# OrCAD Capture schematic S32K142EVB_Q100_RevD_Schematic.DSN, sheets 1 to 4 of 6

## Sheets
1 4. OpenSDA interface: size D; title: S32K142EVB-Q100; rev: D; company: Freescale Semiconductor; note: SCH-29701 PDF: SPF-29701; note: 6501 William Cannon Drive West; note: Austin, TX 78735-8598
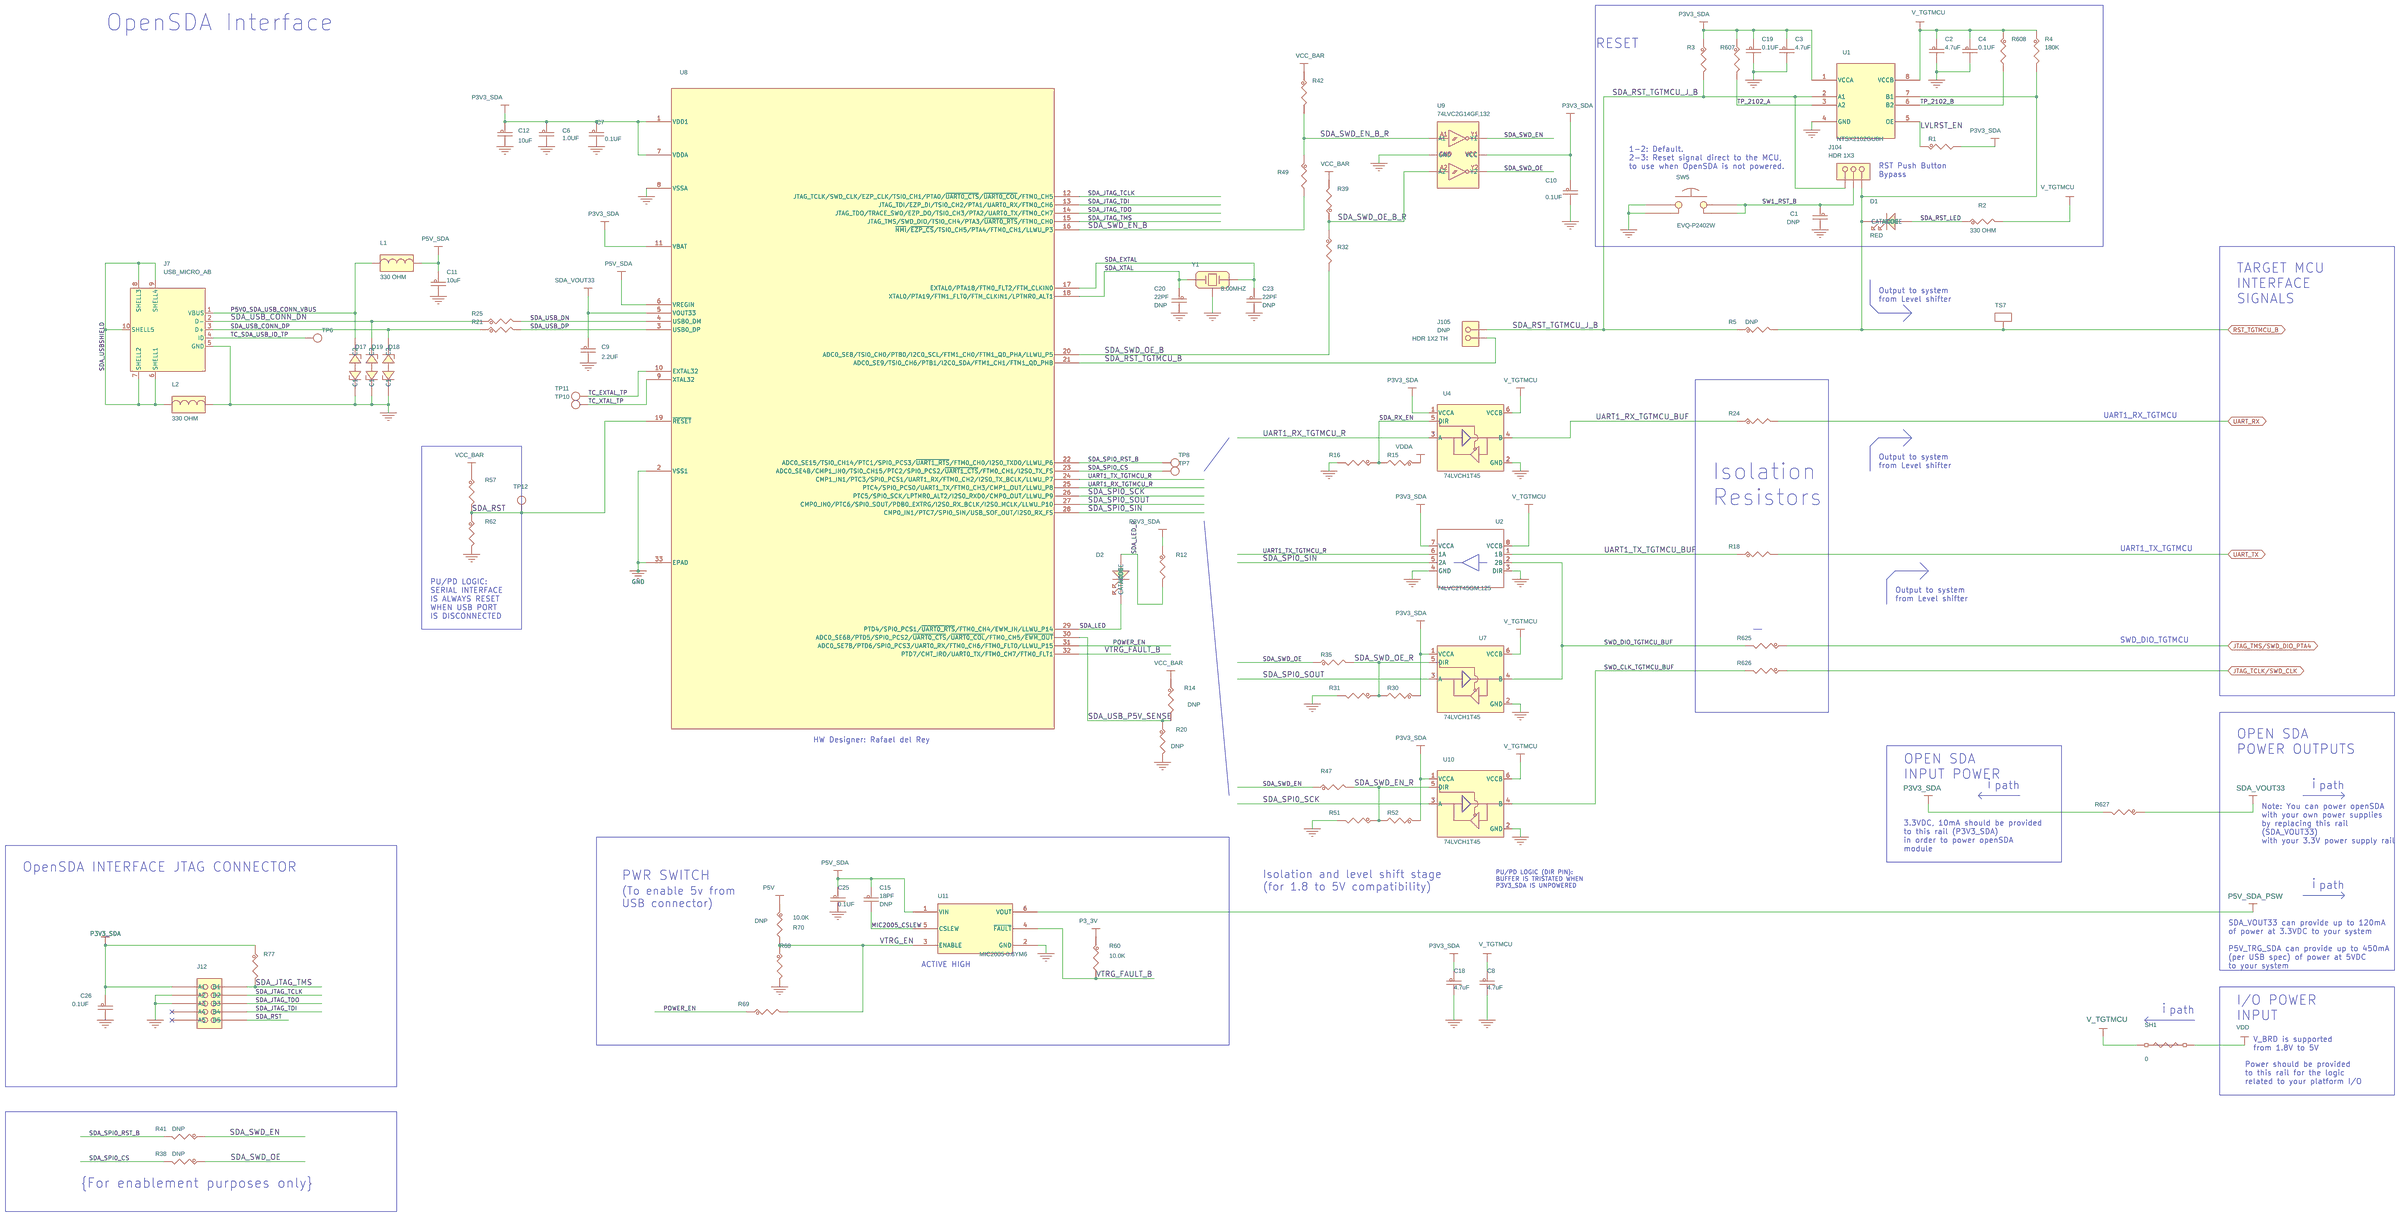
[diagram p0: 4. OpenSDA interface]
2 3. S32K142 MCU: size D; company: NXP Semiconductors
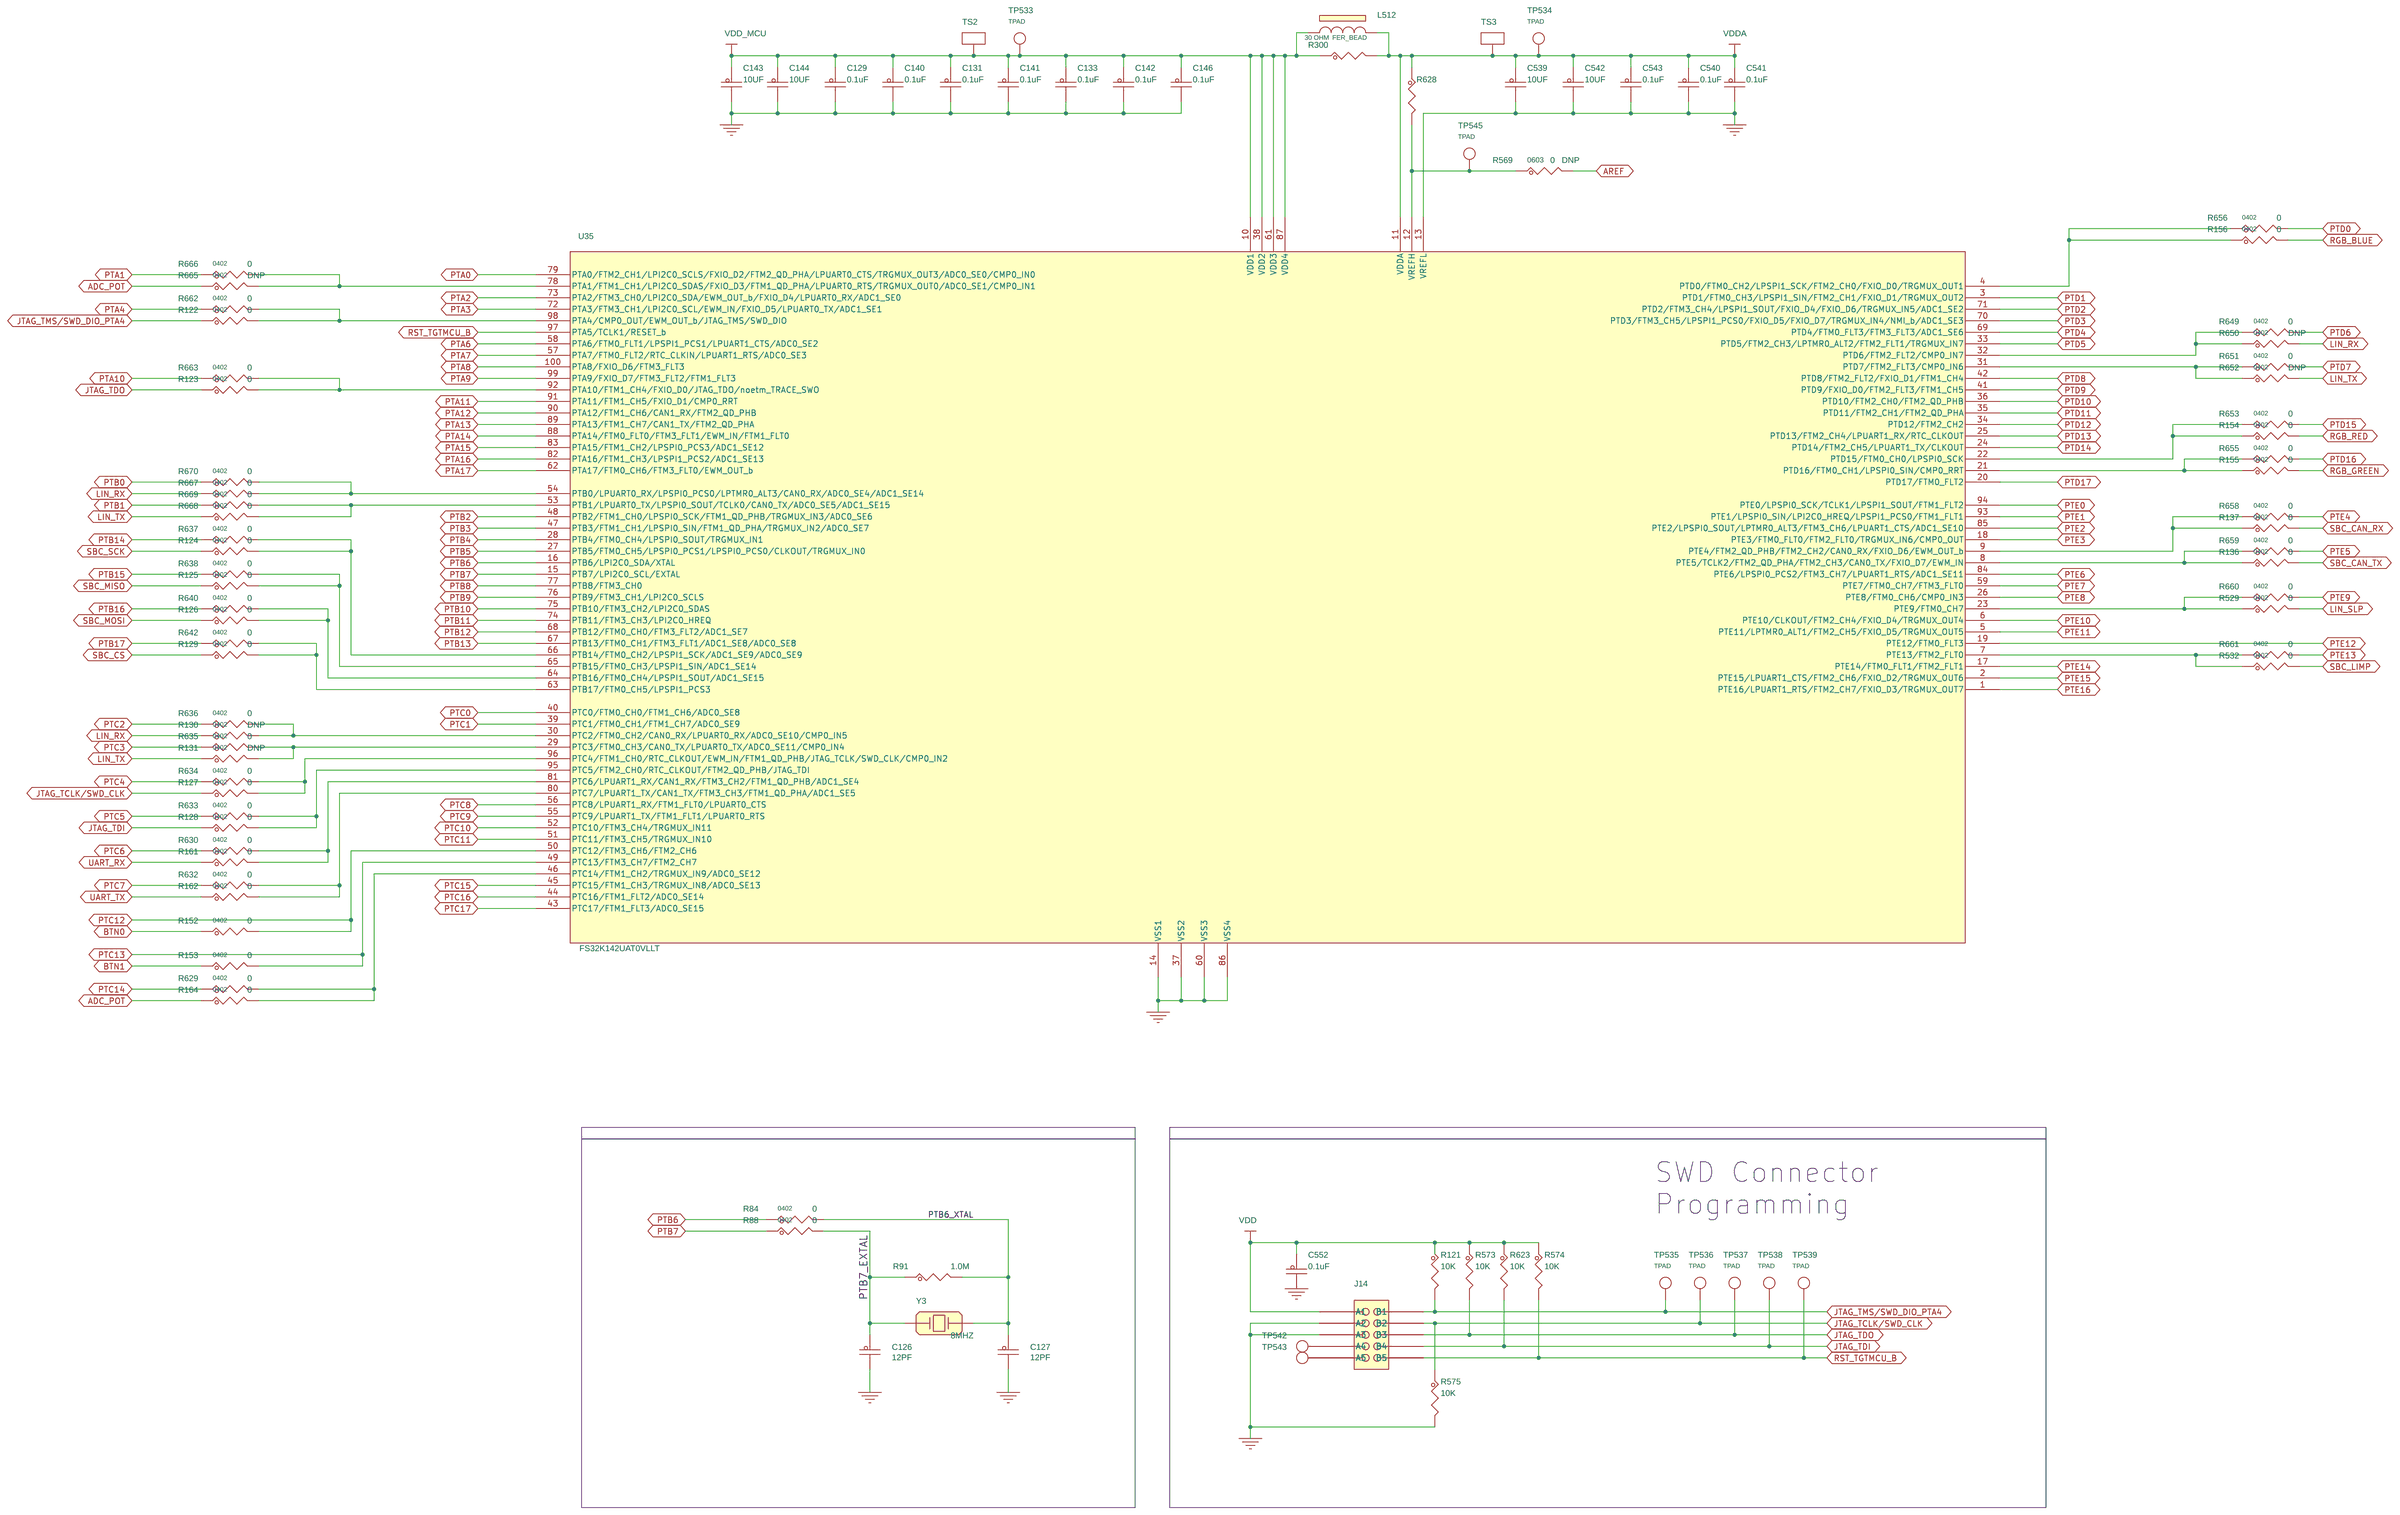
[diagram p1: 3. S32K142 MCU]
3 2. Notes and Block Diagram: company: NXP Semiconductors
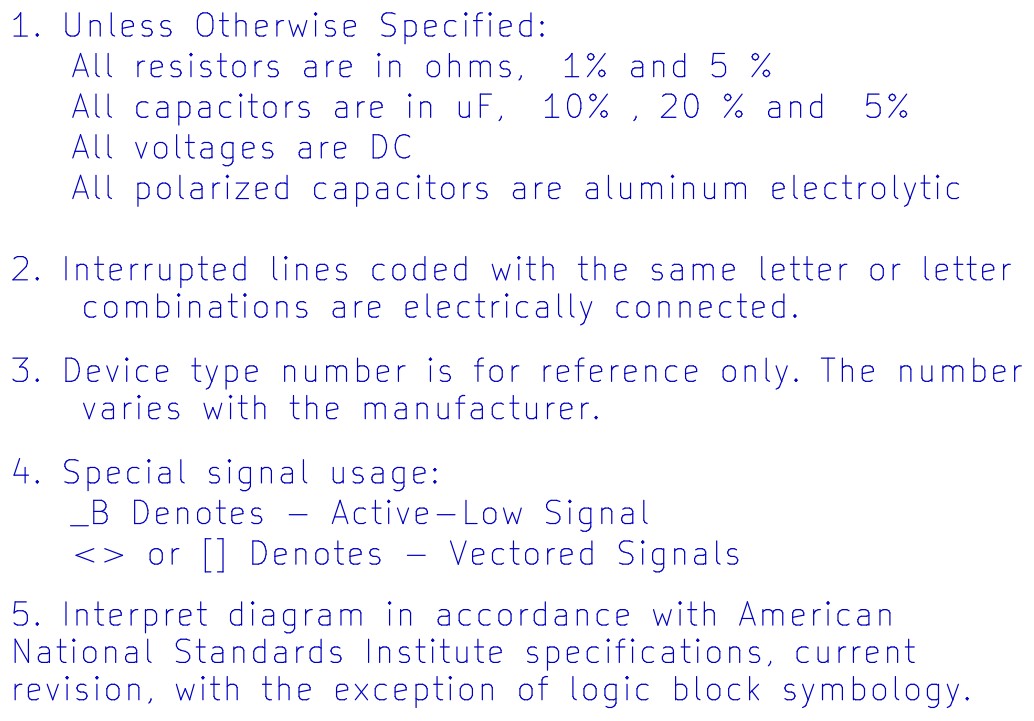
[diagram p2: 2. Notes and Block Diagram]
4 1. Title Page: company: NXP Semiconductors
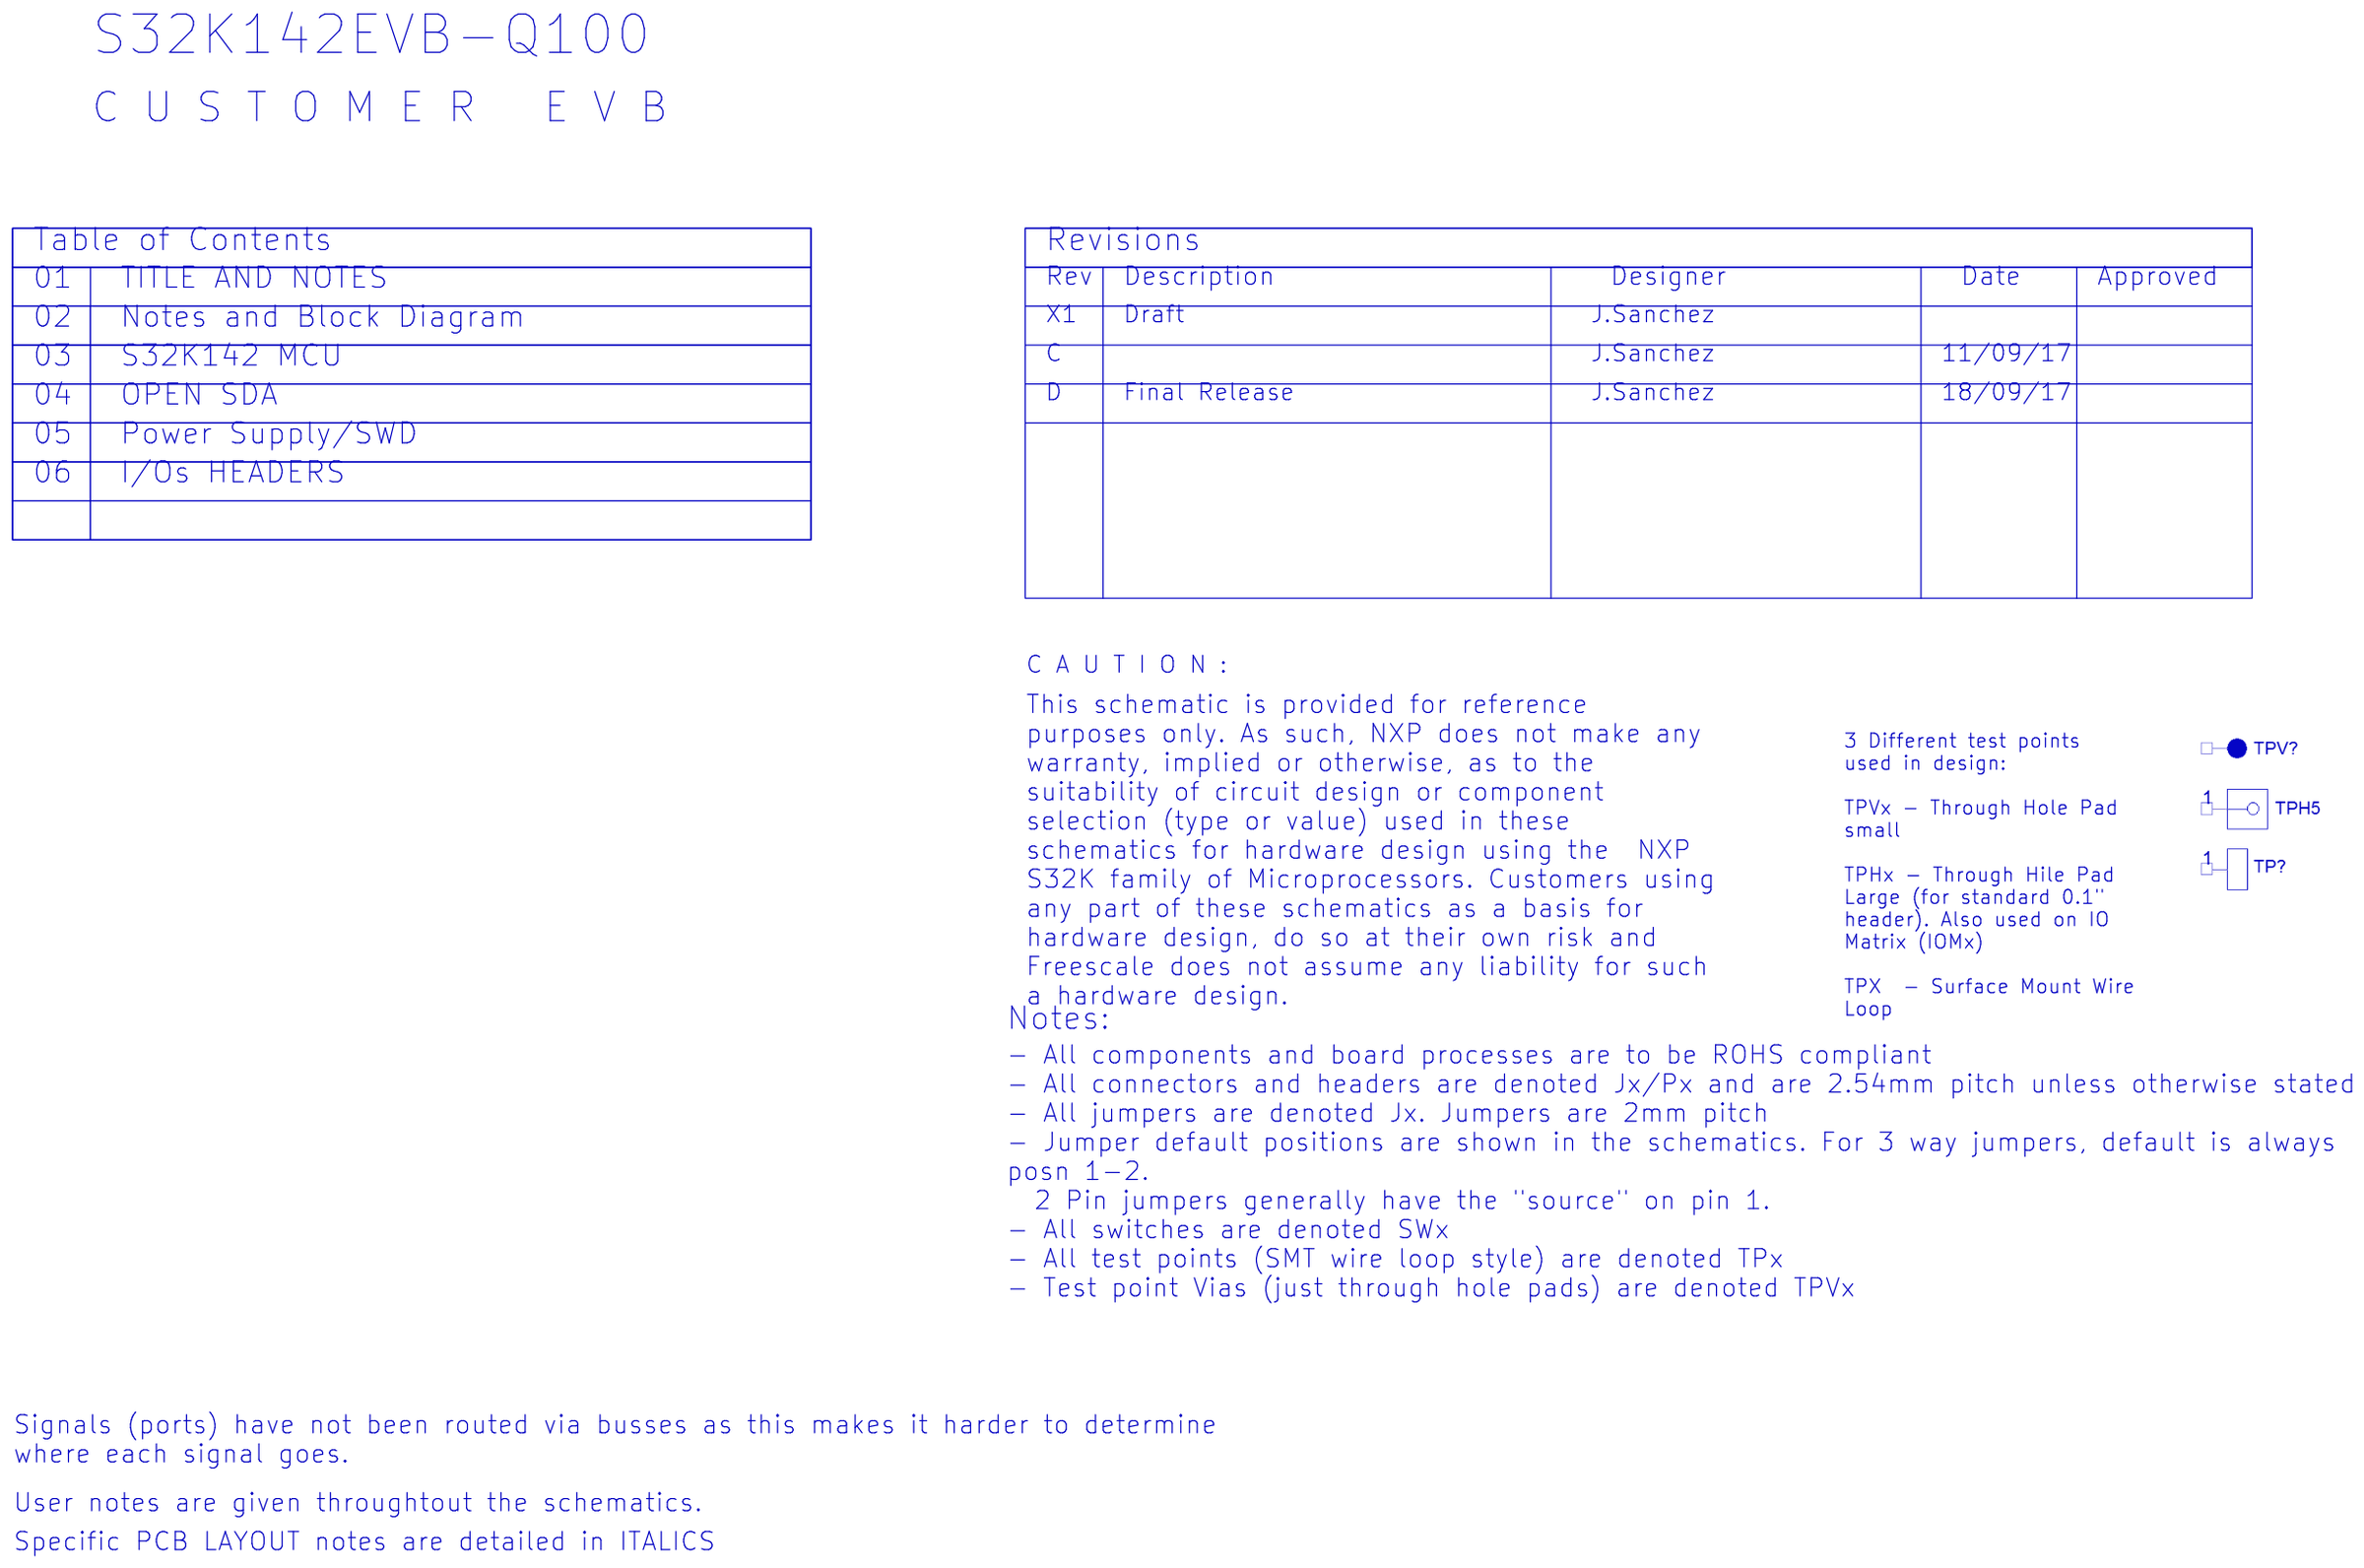
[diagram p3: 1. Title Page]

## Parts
sheet 3. S32K142 MCU
C126  12PF  [CC0402_25]
C127  12PF  [CC0402_25]
C129  0.1uF  [CC0402_25]
C131  0.1uF  [CC0402_25]
C133  0.1uF  [CC0402_25]
C140  0.1uF  [CC0402_25]
C141  0.1uF  [CC0402_25]
C142  0.1uF  [CC0402_25]
C143  10UF  [CC0805_OV]
C144  10UF  [CC0805_OV]
C146  0.1uF  [CC0402_25]
C539  10UF  [CC0805_OV]
C540  0.1uF  [CC0402_25]
C541  0.1uF  [CC0402_25]
C542  10UF  [CC0805_OV]
C543  0.1uF  [CC0402_25]
C552  0.1uF  [CC0402_25]
J14  HDR 2X5  [CON_2RH_10_50]
L512  30 OHM  [IND_0402]
R84  0  [RC0402_25]
R88  0  [RC0402_25]
R91  1.0M  [RC0603_OV]
R121  10K  [RC0402_25]
R122  0  [RC0402_25]
R123  0  [RC0402_25]
R124  0  [RC0402_25]
R125  0  [RC0402_25]
R126  0  [RC0402_25]
R127  0  [RC0402_25]
R128  0  [RC0402_25]
R129  0  [RC0402_25]
R130  0  [RC0402_25]
R131  0  [RC0402_25]
R136  0  [RC0402_25]
R137  0  [RC0402_25]
R152  0  [RC0402_25]
R153  0  [RC0402_25]
R154  0  [RC0402_25]
R155  0  [RC0402_25]
R156  0  [RC0402_25]
R161  0  [RC0402_25]
R162  0  [RC0402_25]
R164  0  [RC0402_25]
R300  0  [RC0603_OV]
R529  0  [RC0402_25]
R532  0  [RC0402_25]
R569  0  [RC0603_OV]
R573  10K  [RC0402_25]
R574  10K  [RC0402_25]
R575  10K  [RC0402_25]
R623  10K  [RC0402_25]
R628  0  [RC0603_OV]
R629  0  [RC0402_25]
R630  0  [RC0402_25]
R632  0  [RC0402_25]
R633  0  [RC0402_25]
R634  0  [RC0402_25]
R635  0  [RC0402_25]
R636  0  [RC0402_25]
R637  0  [RC0402_25]
R638  0  [RC0402_25]
R640  0  [RC0402_25]
R642  0  [RC0402_25]
R649  0  [RC0402_25]
R650  0  [RC0402_25]
R651  0  [RC0402_25]
R652  0  [RC0402_25]
R653  0  [RC0402_25]
R655  0  [RC0402_25]
R656  0  [RC0402_25]
R658  0  [RC0402_25]
R659  0  [RC0402_25]
R660  0  [RC0402_25]
R661  0  [RC0402_25]
R662  0  [RC0402_25]
R663  0  [RC0402_25]
R665  0  [RC0402_25]
R666  0  [RC0402_25]
R667  0  [RC0402_25]
R668  0  [RC0402_25]
R669  0  [RC0402_25]
R670  0  [RC0402_25]
TP533  TPAD_030  [TPAD_030]
TP534  TPAD_030  [TPAD_030]
TP535  TPAD_030  [TPAD_030]
TP536  TPAD_030  [TPAD_030]
TP537  TPAD_030  [TPAD_030]
TP538  TPAD_030  [TPAD_030]
TP539  TPAD_030  [TPAD_030]
TP542  TPAD_030  [TPAD_030]
TP543  TPAD_030  [TPAD_030]
TP545  TPAD_030  [TPAD_030]
TS2  TESTLOOP  [testpoint_135_070mil]
TS3  TESTLOOP  [testpoint_135_070mil]
U35  FS32K142UAT0VLLT  [LQFP100_0P5_14X14]
Y3  8MHZ  [xtal2_3p3x2p6]
sheet 4. OpenSDA interface
C1  1000pF  [CC0402_25]
C2  4.7uF  [CC0402_25]
C3  4.7uF  [CC0402_25]
C4  0.1UF  [CC0402_25]
C6  1.0UF  [CC0402_25]
C7  0.1UF  [CC0402_25]
C8  4.7uF  [CC0402_25]
C9  2.2UF  [CC0603_OV]
C10  0.1UF  [CC0402_25]
C11  10uF  [CC0402_25]
C12  10uF  [CC0603_OV]
C15  18PF  [CC0603_OV]
C18  4.7uF  [CC0402_25]
C19  0.1UF  [CC0402_25]
C20  22PF  [CC0402_25]
C23  22PF  [CC0402_25]
C25  0.1UF  [CC0402_25]
C26  0.1UF  [CC0402_25]
D1  RED  [LED_0603]
D2  LED GREEN  [LED_0603]
D17  PESD5V0R1BSF  [dsn0603-2]
D18  PESD5V0R1BSF  [dsn0603-2]
D19  PESD5V0R1BSF  [dsn0603-2]
J7  USB_MICRO_AB  [con_microab_10f_25_sm_ra]
J12  HDR 2X5  [CON_2RH_10_50]
J104  HDR 1X3  [HDR103_A]
J105  HDR 1X2 TH  [SH_HDR102_BOTTOM]
L1  330 OHM  [ind_1608]
L2  330 OHM  [ind_1608]
R1  4.7K  [RC0402_25]
R2  330 OHM  [RC0402_25]
R3  10.0K  [RC0402_25]
R4  180K  [RC0402_25]
R5  0  [RC0402_25]
R12  220  [RC0603_OV]
R14  4.7K  [RC0402_25]
R15  4.7K  [RC0402_25]
R16  10.0K  [RC0402_25]
R18  0  [RC0402_25]
R20  10.0K  [RC0402_25]
R21  33  [RC0402_25]
R24  0  [RC0402_25]
R25  33  [RC0402_25]
R30  4.7K  [RC0402_25]
R31  10.0K  [RC0402_25]
R32  0  [RC0402_25]
R35  0  [RC0402_25]
R38  0  [RC0402_25]
R39  10.0K  [RC0402_25]
R41  0  [RC0402_25]
R42  10.0K  [RC0402_25]
R47  0  [RC0402_25]
R49  0  [RC0402_25]
R51  10.0K  [RC0402_25]
R52  4.7K  [RC0402_25]
R57  4.7K  [RC0402_25]
R60  10.0K  [RC0402_25]
R62  10.0K  [RC0402_25]
R68  15K  [RC0402_25]
R69  1.0K  [RC0402_25]
R70  10.0K  [RC0402_25]
R77  10.0K  [RC0402_25]
R607  10.0K  [RC0402_25]
R608  10.0K  [RC0402_25]
R625  0  [RC0603_OV]
R626  0  [RC0603_OV]
R627  0  [RC0603_OV]
SH1  0  [SH0603]
SW5  EVQ-P2402W  [sw4_spst_4p8X3p6_2p5]
TP6  TPAD_030  [TPAD_030]
TP7  TPAD_030  [TPAD_030]
TP8  TPAD_030  [TPAD_030]
TP10  TPAD_030  [TPAD_030]
TP11  TPAD_030  [TPAD_030]
TP12  TPAD_030  [TPAD_030]
TS7  TESTLOOP  [testpoint_135_070mil]
U1  NTSX2102GU8H  [xqfn8_1p45x1p25mm]
U2  74LVC2T45GM,125  [qfn8_1p6x1p6mm]
U4  74LVCH1T45  [udfn6_1x1p5mm]
U7  74LVCH1T45  [udfn6_1x1p5mm]
U8  MK20DX128VFM5  [QFN32_S142EP]
U9  74LVC2G14GF,132  [SOT891_6P_0P35_1P05X1P05]
U10  74LVCH1T45  [udfn6_1x1p5mm]
U11  MIC2005-0.8YM6  [SOT23-6_a]
Y1  8.00MHZ  [xtal3_3p35x1p45_sm]

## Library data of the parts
C126 C127 = CAP_NP: CAP CER 12PF 50V 5% C0G 0402; AGILE_PN: 150-75680; CAD_APPROVED: Yes; FPLIST: CC0402_25,CC0402_HD,0402_CC; HEIGHT: 0.55MM; MFG_NAME01: MURATA; MFG_PN01: GRM1555C1H120JZ01D; ROHS: Yes; Tolerance: 5%; VOLTAGE: 50V
C129 C131 C133 C140-C142 C146 C540 C541 C543 C552 = CAP_NP: CAP CER 0.1uF 50V 10% X7R 0402; AGILE_PN: 150-79069; CAD_APPROVED: Yes; FPLIST: CC0402_25,CC0402_HD,0402_CC; HEIGHT: 0.55MM; MFG_NAME01: MURATA; MFG_PN01: GRM155R71H104KE14D; ROHS: Yes; Tolerance: 10%; VOLTAGE: 50V
C143 C144 C539 C542 = CAP_NP: CAP CER 10UF 10V 10% X7R 0805; AGILE_PN: 150-78501; CAD_APPROVED: Yes; FPLIST: CC0603_OV,CC0603,0603_CC; HEIGHT: 1.4MM; MFG_NAME01: Murata; MFG_PN01: GRM21BR71A106KE51L; ROHS: Yes; Tolerance: 10%; VOLTAGE: 10V
J12 J14 = CONN_HDR_5X2: CONN,HEAD,2X5,STR,50/50 CON-2RH-10-50; AGILE_PN: 210-07961-00; CAD_APPROVED: Yes; FPLIST: CON_2RH_10_50,con_2rh_10_50_nsp; HEIGHT: 3.91 MM; MFG_NAME01: SAMTEC; MFG_PN01: FTS-105-01-F-D; ROHS: Yes
L512 = INDUCTOR_FERRITE: IND FER BEAD 30 OHM@100MHZ 2.2A 25% 0402; AGILE_PN: 180-77768; CAD_APPROVED: Yes; FPLIST: IND_0402,0402_CC; HEIGHT: 0.55MM; MFG_NAME01: Murata; MFG_PN01: BLM15PD300SN1D; PART_TYPE: FERRITE\BEAD; ROHS: Yes; Tolerance: 25%; _DESC: FER_BEAD
R84 R88 R122-R129 R136 R137 R152-R156 R161 R162 R164 R529 R532 R629 R630 R632-R638 R640 R642 R649 R651 R653 R655 R656 R658-R663 R666-R670 = RES: RES MF ZERO OHM 1/16W -- AEC-Q200 0402; AGILE_PN: 470-80742; CAD_APPROVED: Yes; FPLIST: RC0402_25,RC0402_HD,0402_CC; HEIGHT: 0.45 MM; MFG_NAME01: VISHAY INTERTECHNOLOGY; MFG_PN01: CRCW04020000Z0ED; PCKG: 0402; ROHS: Yes
R91 = RES: RES MF 1.0M 1/10W 1% 0603; AGILE_PN: 470-76249; CAD_APPROVED: Yes; FPLIST: RC0603_OV,RC0603,0603_CC; HEIGHT: 0.6mm; MFG_NAME01: WALSIN TECHNOLOGY CORP.; MFG_PN01: WR06X1004FTL; ROHS: Yes; Tolerance: 1%
R121 R573-R575 R623 = RES: RES MF 10K 1/8W 1% AEC-Q200 0402; AGILE_PN: 470-80881; CAD_APPROVED: Yes; FPLIST: RC0402_25,RC0402_HD,0402_CC; HEIGHT: 0.4MM; MFG_NAME01: VISHAY INTERTECHNOLOGY; MFG_PN01: CRCW040210K0FKEDHP; ROHS: Yes; Tolerance: 1%
R130 R131 R650 R652 R665 = RES: RES MF ZERO OHM 1/16W -- AEC-Q200 0402; AGILE_PN: 470-80742; ASSY_OPT: DNP; CAD_APPROVED: Yes; FPLIST: RC0402_25,RC0402_HD,0402_CC; HEIGHT: 0.45 MM; MFG_NAME01: VISHAY INTERTECHNOLOGY; MFG_PN01: CRCW04020000Z0ED; PCKG: 0402; ROHS: Yes
R300 R625-R628 = RES: RES MF ZERO OHM 1/10W -- AEC-Q200 0603; AGILE_PN: 470-75407; CAD_APPROVED: Yes; FPLIST: RC0603_OV,RC0603,R603-X2,0603_CC; HEIGHT: 0.6MM; MFG_NAME01: KOA SPEER; MFG_PN01: RK73Z1JTTD; ROHS: Yes; Tolerance: 1%
R569 = RES: RES MF ZERO OHM 1/10W -- AEC-Q200 0603; AGILE_PN: 470-75407; ASSY_OPT: DNP; CAD_APPROVED: Yes; FPLIST: RC0603_OV,RC0603,R603-X2,0603_CC; HEIGHT: 0.6MM; MFG_NAME01: KOA SPEER; MFG_PN01: RK73Z1JTTD; PCKG: 0603; ROHS: Yes; Tolerance: 1%
TP533-TP539 TP542 TP543 TP545 = TESTLOOP: TEST POINT PAD 30MIL DIA SMT, NO PART TO ORDER; AGILE_PN: 211-76642; CAD_APPROVED: Yes; HEIGHT: 0.1MM; MFG_NAME01: NOTACOMPONENT; MFG_PN01: NOTACOMPONENT; NOTE: TPAD; ROHS: Yes
TS2 TS3 TS7 = TEST_POINT_4: TEST POINT PAD SIZE 3.4MM X 1.8MM SMT; AGILE_PN: 211-75906; CAD_APPROVED: Yes; HEIGHT: 1.53 MM; MFG_NAME01: KEYSTONE ELECTRONICS; MFG_PN01: 5015; PRIORITY_PN: 922-00014; ROHS: Yes
U35 = PS32K142_LQFP_1: IC MCU 256K FLASH 2.7-5.5V 112MHZ LQFP100; AGILE_PN: TMP-WF-31607; CAD_APPROVED: Yes; HEIGHT: 1.7 MM; MFG_NAME01: NXP SEMICONDUCTORS; PRE_APN: 344-02268; ROHS: Yes; Temp_Range: -40C to +105C
Y3 = XTAL_CS10: XTAL 8MHZ 8pF AEC-Q200 SMD; AGILE_PN: 230-77981; CAD_APPROVED: Yes; HEIGHT: 1MM; MFG_NAME01: NDK; MFG_PN01: NX3225GD-8MHZ-STD-CRA-3; ROHS: Yes
C1 = CAP_NP: CAP CER 1000PF 50V 5% C0G 0402; AGILE_PN: 150-76334; ASSY_OPT: DNP; CAD_APPROVED: Yes; FPLIST: CC0402_25,CC0402_HD,0402_CC; HEIGHT: 0.55MM; MFG_NAME01: MURATA; MFG_PN01: GRM1555C1H102JA01D; ROHS: Yes; Tolerance: 5%; VOLTAGE: 50V
C2 C3 C8 C18 = CAP_NP: CAP CER 4.7UF 6.3V 20% X5R 0402; AGILE_PN: 150-78463; CAD_APPROVED: Yes; FPLIST: CC0402_25,CC0402_HD,0402_CC; HEIGHT: 0.65MM; MFG_NAME01: TDK; MFG_PN01: C1005X5R0J475M050BC; PRIORITY_PN: 021-00169; ROHS: Yes; SIGNAL_MODEL: DEFAULT_CAPACITOR_4.7e+06pF_2_1; TOL: 10%; Tolerance: 20%; VOLTAGE: 6.3V
C4 C7 C10 C19 C25 C26 = CAP_NP: CAP CER 0.1UF 10V 10% X5R 0402; AGILE_PN: 150-75634; CAD_APPROVED: Yes; FPLIST: CC0402_25,CC0402_HD,0402_CC; HEIGHT: 0.64MM; MFG_NAME01: KEMET; MFG_PN01: C0402C104K8PAC; PRIORITY_PN: 021-00169; ROHS: Yes; SIGNAL_MODEL: DEFAULT_CAPACITOR_100000pF_2_1; TOL: 10%; Tolerance: 10%; VOLTAGE: 10V
C6 = CAP_NP: CAP CER 1.0UF 10V 10% X5R 0402; AGILE_PN: 150-75772; CAD_APPROVED: Yes; FPLIST: CC0402_25,CC0402_HD,0402_CC; HEIGHT: 0.6MM; MFG_NAME01: YAGEO AMERICA; MFG_PN01: CC0402KRX5R6BB105; PRIORITY_PN: 021-00242; ROHS: Yes; SIGNAL_MODEL: DEFAULT_CAPACITOR_1e+06pF_2_1; VOLTAGE: 10V
C9 = CAP_NP: CAP CER 2.2UF 10V 10% X7R 0603; AGILE_PN: 150-78564; CAD_APPROVED: Yes; FPLIST: CC0603_OV,CC0603,0603_CC; HEIGHT: 1.25MM; MFG_NAME01: TAIYO YUDEN; MFG_PN01: LMK107B7225KA-T; ROHS: Yes; SIGNAL_MODEL: DEFAULT_CAPACITOR_2.2e+06pF_2_1; Tolerance: 10%; VOLTAGE: 10V
C11 = CAP_NP: CAP CER 10uF 10V 20% X5R 0402; AGILE_PN: 150-79255; CAD_APPROVED: Yes; FPLIST: C0402_25,CC0402_HD,0402_CC; HEIGHT: 0.7MM; MFG_NAME01: SAMSUNG; MFG_PN01: CL05A106MP5NUNC; PRIORITY_PN: 021-00242; ROHS: Yes; SIGNAL_MODEL: DEFAULT_CAPACITOR_1e+06pF_2_1; Tolerance: 20%; VOLTAGE: 10V
C12 = CAP_NP: CAP CER 10uF 16V 20% X5R 0603; AGILE_PN: 150-79092; CAD_APPROVED: Yes; FPLIST: CC0603_OV,CC0603,0603_CC; HEIGHT: 1mm; MFG_NAME01: TAIYO YUDEN; MFG_PN01: EMK107BBJ106MA-T; ROHS: Yes; SIGNAL_MODEL: DEFAULT_CAPACITOR_1e+07pF_2_1; TOL: 10%; Tolerance: 20%; VOLTAGE: 16V
C15 = CAP_NP: CAP CER 18PF 50V 5% C0G 0603; AGILE_PN: 150-75116; ASSY_OPT: DNP; CAD_APPROVED: Yes; FPLIST: CC0603_OV,CC0603,0603_CC; HEIGHT: 0.90MM; MFG_NAME01: YAGEO AMERICA; MFG_PN01: CC0603JRNPO9BN180; PRIORITY_PN: 021-00320; ROHS: Yes; SIGNAL_MODEL: DEFAULT_CAPACITOR_18.000000pF_2_1; TOL: 5%; Tolerance: 5%; VOLTAGE: 50V
C20 C23 = CAP_NP: CAP CER 22PF 50V 5% C0G 0402; AGILE_PN: 150-75266; ASSY_OPT: DNP; CAD_APPROVED: Yes; FPLIST: CC0402_25,CC0402_HD,0402_CC; HEIGHT: 0.635MM; MFG_NAME01: AVX; MFG_PN01: 04025A220JAT2A; PRIORITY_PN: 021-00234; ROHS: Yes; SIGNAL_MODEL: DEFAULT_CAPACITOR_22.000000pF_2_1; Tolerance: 5%; VOLTAGE: 50V
D1 = LED: LED ULTRA BRIGHT RED SGL 30MA 0603; AGILE_PN: 370-75079; CAD_APPROVED: Yes; HEIGHT: 0.9MM; MFG_NAME01: LITE ON; MFG_PN01: LTST-C190KRKT; ROHS: Yes
D2 = LED: LED GRN SGL 20MA 0603; AGILE_PN: 370-76565; CAD_APPROVED: Yes; HEIGHT: 0.67MM; MFG_NAME01: osram; MFG_PN01: LG L29K-G2J1-24-Z; ROHS: Yes
D17-D19 = DIODE_BIDIR: DIODE TVS 5VWM 9.2VC DSN0603-2; AGILE_PN: 480-79664; CAD_APPROVED: Yes; HEIGHT: 0.32MM; MFG_NAME01: NXP SEMICONDUCTORS; MFG_PN01: PESD5V0R1BSFYL; ROHS: Yes
J7 = MICRO_USB_CONN_10PIN: CON 5 USB_MICRO_AB_RECEPTACLE RA SKT SMT 0.65MM SP 122H AU; AGILE_PN: 211-78945; CAD_APPROVED: Yes; HEIGHT: 3.1MM; MFG_NAME01: molex; MFG_PN01: 0475900001; ROHS: Yes
J104 = CONN_HDR_3X1: HDR 1X3 TH 2.54MM SP 344H AU 118L; AGILE_PN: 210-80732; CAD_APPROVED: Yes; HEIGHT: 8.74MM; MFG_NAME01: Shenzhen JXT Technology Co., Ltd.; MFG_PN01: JT254-D180-103-001; PRIORITY_PN: 028-00700; ROHS: Yes
J105 = CONN_HDR_2X1: HDR 1X2 TH 100MIL SP 339H AU 98L; AGILE_PN: 210-75439; ASSY_OPT: DNP; CAD_APPROVED: YES; FPLIST: HDR102,SH_HDR102_BOTTOM; HEIGHT: 8.71 MM; MFG_NAME01: SAMTEC; MFG_PN01: TSW-102-07-G-S; PRIORITY_PN: 028-00556; ROHS: Yes
L1 L2 = BEAD: IND FER BEAD 330OHM@100MHZ 1.7A 0603; AGILE_PN: 180-78156; CAD_APPROVED: Yes; FPLIST: ind_1608,0603_CC; HEIGHT: 0.95MM; MFG_NAME01: TDK; MFG_PN01: MPZ1608S331A; PART_TYPE: FERRITE\BEAD; ROHS: Yes; Tolerance: 25%
R1 R15 R30 R52 R57 = RES: RES MF 4.7K 1/16W 5% 0402; AGILE_PN: 470-75626; CAD_APPROVED: Yes; FPLIST: RC0402_25,RC0402_HD,0402_CC; HEIGHT: 0.41mm; MFG_NAME01: KOA SPEER; MFG_PN01: RK73B1ETTP472J; ROHS: Yes; SIGNAL_MODEL: DEFAULT_RESISTOR_4700OHM_2_1; TOL: 1%; Tolerance: 5%
R2 = RES: RES MF 330 OHM 1/16W 1% 0402; AGILE_PN: 470-80566; CAD_APPROVED: Yes; FPLIST: RC0402_25,RC0402_HD,0402_CC; HEIGHT: 0.4MM; MFG_NAME01: WALSIN TECHNOLOGY CORP.; MFG_PN01: WR04X3300FTL; ROHS: Yes; Tolerance: 1%
R3 R16 R31 R39 R42 R51 R607 R608 = RES: RES MF 10.0K 1/16W 1% AEC-Q200 0402; AGILE_PN: 470-75416; CAD_APPROVED: Yes; FPLIST: RC0402_25,RC0402_HD,0402_CC; HEIGHT: 0.4MM; MFG_NAME01: KOA SPEER; MFG_PN01: RK73H1ETTP1002F; PRIORITY_PN: 006-00552; ROHS: Yes; SIGNAL_MODEL: DEFAULT_RESISTOR_10000OHM_2_1; TOL: 5%; Tolerance: 1%
R4 = RES: RES MF 180K  1/16W 1% 0402; AGILE_PN: 470-31088; CAD_APPROVED: Yes; FPLIST: RC0402_25,RC0402_HD,0402_CC; HEIGHT: 0.40 MM; MFG_NAME01: KOA SPEER; MFG_PN01: RK73H1ETTP1803F; ROHS: Yes; SIGNAL_MODEL: DEFAULT_RESISTOR_180000OHM_2_1; Tolerance: 1%
R5 = RES: RES MF ZERO OHM 1/16W -- AEC-Q200 0402; AGILE_PN: 470-80742; ASSY_OPT: DNP; CAD_APPROVED: Yes; FPLIST: RC0402_25,RC0402_HD,0402_CC; HEIGHT: 0.45 MM; MFG_NAME01: VISHAY INTERTECHNOLOGY; MFG_PN01: CRCW04020000Z0ED; PRIORITY_PN: 006-00559; ROHS: Yes; SIGNAL_MODEL: DEFAULT_RESISTOR_0.001OHM_2_1; TOL: 5%; VOLTAGE: 1/16W
R12 = RES: RES MF 220 OHM 1/10W 5% 0603; AGILE_PN: 470-30297; CAD_APPROVED: Yes; FPLIST: RC0603_OV,RC0603,0603_CC; HEIGHT: 0.6MM; MFG_NAME01: KOA SPEER; MFG_PN01: RK73B1JTTD221J; ROHS: Yes; SIGNAL_MODEL: DEFAULT_RESISTOR_220.000000OHM_2_1; Tolerance: 5%
R14 = RES: RES MF 4.7K 1/16W 5% 0402; AGILE_PN: 470-75626; ASSY_OPT: DNP; CAD_APPROVED: Yes; FPLIST: RC0402_25,RC0402_HD,0402_CC; HEIGHT: 0.41mm; MFG_NAME01: KOA SPEER; MFG_PN01: RK73B1ETTP472J; ROHS: Yes; SIGNAL_MODEL: DEFAULT_RESISTOR_4700OHM_2_1; TOL: 1%; Tolerance: 5%
R18 R24 = RES: RES MF ZERO OHM 1/16W -- AEC-Q200 0402; AGILE_PN: 470-80742; CAD_APPROVED: Yes; FPLIST: RC0402_25,RC0402_HD,0402_CC; HEIGHT: 0.45 MM; MFG_NAME01: VISHAY INTERTECHNOLOGY; MFG_PN01: CRCW04020000Z0ED; PRIORITY_PN: 006-00559; ROHS: Yes; SIGNAL_MODEL: DEFAULT_RESISTOR_0.001OHM_2_1; TOL: 5%; VOLTAGE: 1/16W
R20 = RES: RES MF 10.0K 1/16W 1% AEC-Q200 0402; AGILE_PN: 470-75416; ASSY_OPT: DNP; CAD_APPROVED: Yes; FPLIST: RC0402_25,RC0402_HD,0402_CC; HEIGHT: 0.4MM; MFG_NAME01: KOA SPEER; MFG_PN01: RK73H1ETTP1002F; PRIORITY_PN: 006-00552; ROHS: Yes; SIGNAL_MODEL: DEFAULT_RESISTOR_10000OHM_2_1; Tolerance: 1%
R21 R25 = RES: RES MF 33.0 OHM 1/16W 1% 0402; AGILE_PN: 470-75790; CAD_APPROVED: Yes; FPLIST: RC0402_25,RC0402_HD,RC0402_X2,0402_CC; HEIGHT: 0.4MM; MFG_NAME01: THYE MING TECH CO LTD; MFG_PN01: CR-02FL6---33R; PRIORITY_PN: 006-00556; ROHS: Yes; SIGNAL_MODEL: DEFAULT_RESISTOR_33.000000OHM_2_1; Tolerance: 1%
R32 R35 R47 R49 = RES: RES MF ZERO OHM 1/16W -- AEC-Q200 0402; AGILE_PN: 470-80742; CAD_APPROVED: Yes; FPLIST: RC0402_25,RC0402_HD,0402_CC; HEIGHT: 0.45 MM; MFG_NAME01: VISHAY INTERTECHNOLOGY; MFG_PN01: CRCW04020000Z0ED; PRIORITY_PN: 006-00559; ROHS: Yes; SIGNAL_MODEL: DEFAULT_RESISTOR_0.001OHM_2_1; VOLTAGE: 1/16W
R38 R41 = RES: RES MF ZERO OHM 1/16W -- AEC-Q200 0402; AGILE_PN: 470-80742; ASSY_OPT: DNP; CAD_APPROVED: Yes; FPLIST: RC0402_25,RC0402_HD,0402_CC; HEIGHT: 0.45 MM; MFG_NAME01: VISHAY INTERTECHNOLOGY; MFG_PN01: CRCW04020000Z0ED; PRIORITY_PN: 006-00559; ROHS: Yes; SIGNAL_MODEL: DEFAULT_RESISTOR_0.001OHM_2_1; VOLTAGE: 1/16W
R60 = RES: RES MF 10.0K 1/16W 1% AEC-Q200 0402; AGILE_PN: 470-75416; CAD_APPROVED: Yes; FPLIST: RC0402_25,RC0402_HD,0402_CC; HEIGHT: 0.4MM; MFG_NAME01: KOA SPEER; MFG_PN01: RK73H1ETTP1002F; PRIORITY_PN: 006-00552; ROHS: Yes; SIGNAL_MODEL: DEFAULT_RESISTOR_10000OHM_2_1; TOL: 1%; Tolerance: 1%
R62 R77 = RES: RES MF 10.0K 1/16W 1% AEC-Q200 0402; AGILE_PN: 470-75416; CAD_APPROVED: Yes; FPLIST: RC0402_25,RC0402_HD,0402_CC; HEIGHT: 0.4MM; MFG_NAME01: KOA SPEER; MFG_PN01: RK73H1ETTP1002F; PRIORITY_PN: 006-00552; ROHS: Yes; SIGNAL_MODEL: DEFAULT_RESISTOR_10000OHM_2_1; Tolerance: 1%
R68 = RES: RES MF 15K  1/16W 1% 0402; AGILE_PN: 470-30965; CAD_APPROVED: Yes; FPLIST: RC0402_25,RC0402_HD,0402_CC; HEIGHT: 0.40 MM; MFG_NAME01: KOA SPEER; MFG_PN01: RK73H1ETTP1502F; ROHS: Yes; SIGNAL_MODEL: DEFAULT_RESISTOR_15000OHM_2_1; TOL: 1%; Tolerance: 1%
R69 = RES: RES MF 1.0K 1/16W 1% 0402; AGILE_PN: 470-76037; CAD_APPROVED: Yes; FPLIST: RC0402_25,RC0402_HD,RC0402_X2,0402_CC; HEIGHT: 0.4MM; MFG_NAME01: YAGEO AMERICA; MFG_PN01: RC0402FR-071KL; PRIORITY_PN: 006-00553; ROHS: Yes; SIGNAL_MODEL: DEFAULT_RESISTOR_1000.000000OHM_2_1; TOL: 1%; Tolerance: 1%; VOLTAGE: 1/16W
R70 = RES: RES MF 10.0K 1/16W 1% AEC-Q200 0402; AGILE_PN: 470-75416; ASSY_OPT: DNP; CAD_APPROVED: Yes; FPLIST: RC0402_25,RC0402_HD,0402_CC; HEIGHT: 0.4MM; MFG_NAME01: KOA SPEER; MFG_PN01: RK73H1ETTP1002F; PRIORITY_PN: 006-00552; ROHS: Yes; SIGNAL_MODEL: DEFAULT_RESISTOR_10000OHM_2_1; TOL: 1%; Tolerance: 1%
SH1 = RES_SHORT-2: ZERO OHM CUT TRACE 0603 PADS; NO PART TO ORDER; AGILE_PN: 470-80018; CAD_APPROVED: Yes; FPLIST: SH0603,SH0603_CC,SH0603-X2_PIN1TO2,SH0603-X2_PIN2TO3; HEIGHT: 0.1MM; MFG_NAME01: LAYOUT ELEMENT ONLY; MFG_PN01: LAYOUT ELEMENT ONLY; ROHS: Yes; SIGNAL_MODEL: DEFAULT_RESISTOR_0.001OHM_2_1
SW5 = EDGE_MOUNT_PB_SW_2: SW SPST PB NO 0.02A 15V SMT; AGILE_PN: 510-77992; CAD_APPROVED: Yes; HEIGHT: 2.7 MM; MFG_NAME01: Panasonic; ROHS: Yes
TP6-TP8 TP10-TP12 = TestLoop: TEST POINT PAD 30MIL DIA SMT, NO PART TO ORDER; AGILE_PN: 211-76642; CAD_APPROVED: Yes; HEIGHT: 0.1MM; MFG_NAME01: NOTACOMPONENT; MFG_PN01: NOTACOMPONENT; ROHS: Yes
U1 = NTSX2102GU8H_8P: IC DUAL SUPPLY XCVR 50 MBPS 5.5V XQFN8; AGILE_PN: 312-80763; CAD_APPROVED: Yes; HEIGHT: 0.5MM; MFG_NAME01: NXP Semiconductors; ROHS: Yes; VOLTAGE: 5.5V
U2 = 74LVC2T45GM_8P: IC XCVR DUAL SUPPLY 1.2 -5.5V XQFN8; AGILE_PN: 312-80762; CAD_APPROVED: Yes; HEIGHT: 0.5MM; MFG_NAME01: NXP Semiconductors; ROHS: Yes; VOLTAGE: 5.5V
U4 U7 U10 = 74LVCH1T45_6P: IC XCVR 1BIT 3-STATE DUAL 1.2-5.5V XSON6; AGILE_PN: 312-80758; CAD_APPROVED: Yes; HEIGHT: 0.5MM; MFG_NAME01: NXP SEMICONDUCTORS; MFG_PN01: 74LVCH1T45GM,132; ROHS: Yes; VOLTAGE: 1.2-5.5V
U8 = PK20DX128V_QFN_32P: IC MCU FLASH 128KB 50MHZ 1.71-3.6V QFN32; AGILE_PN: 344-01231; CAD_APPROVED: Yes; HEIGHT: 1MM; MFG_NAME01: FREESCALE SEMICONDUCTOR; ROHS: Yes; VOLTAGE: 1.71-3.6V
U9 = NC7WP14: IC DUAL INV SCHMITT-TRIG 1.65-5.5V  XSON6; AGILE_PN: 315-80930; CAD_APPROVED: Yes; HEIGHT: 0.5MM; MFG_NAME01: NXP SEMICONDUCTORS; ROHS: Yes
U11 = MIC2005-0.8YM6: IC LIN SW PWR 0.8A 2.5-5.5V SOT23-6; AGILE_PN: 315-79199; CAD_APPROVED: Yes; HEIGHT: 1.45MM; MFG_NAME01: MICREL; PRIORITY_PN: 051-MIC2005-08; ROHS: Yes; VOLTAGE: 2.5-5.5V
Y1 = XTAL_CS: XTAL 8.00MHZ RSN CERAMIC -- SMT; AGILE_PN: 230-77664; CAD_APPROVED: Yes; HEIGHT: 0.8MM; MFG_NAME01: MURATA; MFG_PN01: CSTCE8M00G55-R0; PRIORITY_PN: 048-00290; ROHS: Yes

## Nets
GND: C1.2 C2.2 C3.2 C4.2 C6.2 C7.2 C8.2 C9.2 C10.2 C11.2 C12.2 C18.2 C19.2 C20.2 C23.2 C25.2 C26.2 C126.2 C127.2 C129.2 C131.2 C133.2 C140.2 C141.2 C142.2 C143.2 C144.2 C146.2 C539.2 C540.2 C541.2 C542.2 C543.2 C552.2 D17.1(C1) D18.1(C1) D19.1(C1) J7.5(GND) J12.3(A2) J12.5(A3) J14.3(A2) J14.5(A3) L2.2 R16.2 R20.2 R31.2 R51.2 R62.2 R68.2 R575.2 SW5.1 SW5.3 U1.4(GND) U2.3(DIR) U2.4(GND) U4.2(GND) U7.2(GND) U8.2(VSS1) U8.8(VSSA) U8.33(EPAD) U9.2(GND) U10.2(GND) U11.2(GND) U35.13(VREFL) U35.14(VSS1) U35.37(VSS2) U35.60(VSS3) U35.86(VSS4) Y1.2 ; also on sheet 5 6
P3V3_SDA: C3.1 C6.1 C7.1 C10.1 C12.1 C18.1 C19.1 C26.1 J12.1(A1) R1.2 R3.1 R12.1 R15.1 R30.1 R39.2 R42.1 R52.1 R60.1 R77.1 R607.1 R627.2 U1.1(VCCA) U2.7(VCCA) U4.1(VCCA) U7.1(VCCA) U8.1(VDD1) U8.7(VDDA) U8.11(VBAT) U9.5(VCC) U10.1(VCCA)
P5V0_SDA_USB_CONN_VBUS: D17.2(C2) J7.1(VBUS) L1.1
P5V_SDA: C11.1 C15.1 C25.1 L1.2 R14.1 R57.1 R70.1 U8.6(VREGIN) U11.1(VIN)
P5V_SDA_PSW: U11.6(VOUT) ; also on sheet 5
VDD: C552.1 J14.1(A1) R121.1 R573.1 R574.1 R623.1 SH1.2 ; also on sheet 5 6
VDD_MCU: C129.1 C131.1 C133.1 C140.1 C141.1 C142.1 C143.1 C144.1 C146.1 L512.2 R300.1 TP533.1(Pin1) TS2.1 U35.10(VDD1) U35.38(VDD2) U35.61(VDD3) U35.87(VDD4) ; also on sheet 5
VDDA: C539.1 C540.1 C541.1 C542.1 C543.1 L512.1 R300.2 R628.1 TP534.1(Pin1) TS3.1 U35.11(VDDA)
ADC_POT: R164.1 R665.1 ; also on sheet 6
AREF: R569.2 ; also on sheet 6
BTN0: R152.1 ; also on sheet 6
BTN1: R153.1 ; also on sheet 6
JTAG_TCLK/SWD_CLK: J14.4(B2) R127.1 R575.1 R626.1 TP536.1(Pin1)
JTAG_TDI: J14.8(B4) R128.1 R623.2 TP538.1(Pin1)
JTAG_TDO: J14.6(B3) R123.1 R573.2 TP537.1(Pin1)
JTAG_TMS/SWD_DIO_PTA4: J14.2(B1) R121.2 R122.1 R625.1 TP535.1(Pin1)
LIN_RX: R130.1 R650.2 R667.1 ; also on sheet 5
LIN_SLP: R529.2 ; also on sheet 5
LIN_TX: R131.1 R652.2 R668.1 ; also on sheet 5
LVLRST_EN: R1.1 U1.5(OE)
MIC2005_CSLEW: C15.2 U11.5(CSLEW)
POWER_EN: R69.1 U8.31(ADC0_SE7B/PTD6/SPI0_PCS3/UART0_RX/FTM0_CH6/FTM0_FLT0/LLWU_P15)
PTA0: U35.79(PTA0/FTM2_CH1/LPI2C0_SCLS/FXIO_D2/FTM2_QD_PHA/LPUART0_CTS/TRGMUX_OUT3/ADC0_SE0/CMP0_IN0) ; also on sheet 6
PTA1: R666.1 ; also on sheet 6
PTA2: U35.73(PTA2/FTM3_CH0/LPI2C0_SDA/EWM_OUT_b/FXIO_D4/LPUART0_RX/ADC1_SE0) ; also on sheet 6
PTA3: U35.72(PTA3/FTM3_CH1/LPI2C0_SCL/EWM_IN/FXIO_D5/LPUART0_TX/ADC1_SE1) ; also on sheet 6
PTA4: R662.1 ; also on sheet 6
PTA6: U35.58(PTA6/FTM0_FLT1/LPSPI1_PCS1/LPUART1_CTS/ADC0_SE2) ; also on sheet 6
PTA7: U35.57(PTA7/FTM0_FLT2/RTC_CLKIN/LPUART1_RTS/ADC0_SE3) ; also on sheet 6
PTA8: U35.100(PTA8/FXIO_D6/FTM3_FLT3) ; also on sheet 6
PTA9: U35.99(PTA9/FXIO_D7/FTM3_FLT2/FTM1_FLT3) ; also on sheet 6
PTA10: R663.1 ; also on sheet 6
PTA11: U35.91(PTA11/FTM1_CH5/FXIO_D1/CMP0_RRT) ; also on sheet 6
PTA12: U35.90(PTA12/FTM1_CH6/CAN1_RX/FTM2_QD_PHB) ; also on sheet 6
PTA13: U35.89(PTA13/FTM1_CH7/CAN1_TX/FTM2_QD_PHA) ; also on sheet 6
PTA14: U35.88(PTA14/FTM0_FLT0/FTM3_FLT1/EWM_IN/FTM1_FLT0) ; also on sheet 6
PTA15: U35.83(PTA15/FTM1_CH2/LPSPI0_PCS3/ADC1_SE12) ; also on sheet 6
PTA16: U35.82(PTA16/FTM1_CH3/LPSPI1_PCS2/ADC1_SE13) ; also on sheet 6
PTA17: U35.62(PTA17/FTM0_CH6/FTM3_FLT0/EWM_OUT_b) ; also on sheet 6
PTB0: R670.1 ; also on sheet 6
PTB1: R669.1 ; also on sheet 6
PTB2: U35.48(PTB2/FTM1_CH0/LPSPI0_SCK/FTM1_QD_PHB/TRGMUX_IN3/ADC0_SE6) ; also on sheet 6
PTB3: U35.47(PTB3/FTM1_CH1/LPSPI0_SIN/FTM1_QD_PHA/TRGMUX_IN2/ADC0_SE7) ; also on sheet 6
PTB4: U35.28(PTB4/FTM0_CH4/LPSPI0_SOUT/TRGMUX_IN1) ; also on sheet 6
PTB5: U35.27(PTB5/FTM0_CH5/LPSPI0_PCS1/LPSPI0_PCS0/CLKOUT/TRGMUX_IN0) ; also on sheet 6
PTB6: R84.1 U35.16(PTB6/LPI2C0_SDA/XTAL) ; also on sheet 6
PTB6_XTAL: C127.1 R84.2 R91.2 Y3.2
PTB7: R88.1 U35.15(PTB7/LPI2C0_SCL/EXTAL) ; also on sheet 6
PTB7_EXTAL: C126.1 R88.2 R91.1 Y3.1
PTB8: U35.77(PTB8/FTM3_CH0) ; also on sheet 6
PTB9: U35.76(PTB9/FTM3_CH1/LPI2C0_SCLS) ; also on sheet 6
PTB10: U35.75(PTB10/FTM3_CH2/LPI2C0_SDAS) ; also on sheet 6
PTB11: U35.74(PTB11/FTM3_CH3/LPI2C0_HREQ) ; also on sheet 6
PTB12: U35.68(PTB12/FTM0_CH0/FTM3_FLT2/ADC1_SE7) ; also on sheet 6
PTB13: U35.67(PTB13/FTM0_CH1/FTM3_FLT1/ADC1_SE8/ADC0_SE8) ; also on sheet 6
PTB14: R637.1 ; also on sheet 6
PTB15: R638.1 ; also on sheet 6
PTB16: R640.1 ; also on sheet 6
PTB17: R642.1 ; also on sheet 6
PTC0: U35.40(PTC0/FTM0_CH0/FTM1_CH6/ADC0_SE8) ; also on sheet 6
PTC1: U35.39(PTC1/FTM0_CH1/FTM1_CH7/ADC0_SE9) ; also on sheet 6
PTC2: R636.1 ; also on sheet 6
PTC3: R635.1 ; also on sheet 6
PTC4: R634.1 ; also on sheet 6
PTC5: R633.1 ; also on sheet 6
PTC6: R630.1 ; also on sheet 6
PTC7: R632.1 ; also on sheet 6
PTC8: U35.56(PTC8/LPUART1_RX/FTM1_FLT0/LPUART0_CTS) ; also on sheet 6
PTC9: U35.55(PTC9/LPUART1_TX/FTM1_FLT1/LPUART0_RTS) ; also on sheet 6
PTC10: U35.52(PTC10/FTM3_CH4/TRGMUX_IN11) ; also on sheet 6
PTC11: U35.51(PTC11/FTM3_CH5/TRGMUX_IN10) ; also on sheet 6
PTC12: R152.2 U35.50(PTC12/FTM3_CH6/FTM2_CH6) ; also on sheet 6
PTC13: R153.2 U35.49(PTC13/FTM3_CH7/FTM2_CH7) ; also on sheet 6
PTC14: R629.1 ; also on sheet 6
PTC15: U35.45(PTC15/FTM1_CH3/TRGMUX_IN8/ADC0_SE13) ; also on sheet 6
PTC16: U35.44(PTC16/FTM1_FLT2/ADC0_SE14) ; also on sheet 6
PTC17: U35.43(PTC17/FTM1_FLT3/ADC0_SE15) ; also on sheet 6
PTD0: R656.2 ; also on sheet 6
PTD1: U35.3(PTD1/FTM0_CH3/LPSPI1_SIN/FTM2_CH1/FXIO_D1/TRGMUX_OUT2) ; also on sheet 6
PTD2: U35.71(PTD2/FTM3_CH4/LPSPI1_SOUT/FXIO_D4/FXIO_D6/TRGMUX_IN5/ADC1_SE2) ; also on sheet 6
PTD3: U35.70(PTD3/FTM3_CH5/LPSPI1_PCS0/FXIO_D5/FXIO_D7/TRGMUX_IN4/NMI_b/ADC1_SE3) ; also on sheet 6
PTD4: U35.69(PTD4/FTM0_FLT3/FTM3_FLT3/ADC1_SE6) ; also on sheet 6
PTD5: U35.33(PTD5/FTM2_CH3/LPTMR0_ALT2/FTM2_FLT1/TRGMUX_IN7) ; also on sheet 6
PTD6: R649.2 ; also on sheet 6
PTD7: R651.2 ; also on sheet 6
PTD8: U35.42(PTD8/FTM2_FLT2/FXIO_D1/FTM1_CH4) ; also on sheet 6
PTD9: U35.41(PTD9/FXIO_D0/FTM2_FLT3/FTM1_CH5) ; also on sheet 6
PTD10: U35.36(PTD10/FTM2_CH0/FTM2_QD_PHB) ; also on sheet 6
PTD11: U35.35(PTD11/FTM2_CH1/FTM2_QD_PHA) ; also on sheet 6
PTD12: U35.34(PTD12/FTM2_CH2) ; also on sheet 6
PTD13: U35.25(PTD13/FTM2_CH4/LPUART1_RX/RTC_CLKOUT) ; also on sheet 6
PTD14: U35.24(PTD14/FTM2_CH5/LPUART1_TX/CLKOUT) ; also on sheet 6
PTD15: R653.2 ; also on sheet 6
PTD16: R655.2 ; also on sheet 6
PTD17: U35.20(PTD17/FTM0_FLT2) ; also on sheet 6
PTE0: U35.94(PTE0/LPSPI0_SCK/TCLK1/LPSPI1_SOUT/FTM1_FLT2) ; also on sheet 6
PTE1: U35.93(PTE1/LPSPI0_SIN/LPI2C0_HREQ/LPSPI1_PCS0/FTM1_FLT1) ; also on sheet 6
PTE2: U35.85(PTE2/LPSPI0_SOUT/LPTMR0_ALT3/FTM3_CH6/LPUART1_CTS/ADC1_SE10) ; also on sheet 6
PTE3: U35.18(PTE3/FTM0_FLT0/FTM2_FLT0/TRGMUX_IN6/CMP0_OUT) ; also on sheet 6
PTE4: R658.2 ; also on sheet 6
PTE5: R659.2 ; also on sheet 6
PTE6: U35.84(PTE6/LPSPI0_PCS2/FTM3_CH7/LPUART1_RTS/ADC1_SE11) ; also on sheet 6
PTE7: U35.59(PTE7/FTM0_CH7/FTM3_FLT0) ; also on sheet 6
PTE8: U35.26(PTE8/FTM0_CH6/CMP0_IN3) ; also on sheet 6
PTE9: R660.2 ; also on sheet 6
PTE10: U35.6(PTE10/CLKOUT/FTM2_CH4/FXIO_D4/TRGMUX_OUT4) ; also on sheet 6
PTE11: U35.5(PTE11/LPTMR0_ALT1/FTM2_CH5/FXIO_D5/TRGMUX_OUT5) ; also on sheet 6
PTE12: U35.19(PTE12/FTM0_FLT3) ; also on sheet 6
PTE13: R661.2 ; also on sheet 6
PTE14: U35.17(PTE14/FTM0_FLT1/FTM2_FLT1) ; also on sheet 6
PTE15: U35.2(PTE15/LPUART1_CTS/FTM2_CH6/FXIO_D2/TRGMUX_OUT6) ; also on sheet 6
PTE16: U35.1(PTE16/LPUART1_RTS/FTM2_CH7/FXIO_D3/TRGMUX_OUT7) ; also on sheet 6
RGB_BLUE: R156.2 ; also on sheet 6
RGB_GREEN: R155.2 ; also on sheet 6
RGB_RED: R154.2 ; also on sheet 6
RST_TGTMCU_B: D1.C(CATHODE) J14.10(B5) J104.3 R4.2 R5.2 R574.2 TP539.1(Pin1) TS7.1 U1.7(B1) U35.97(PTA5/TCLK1/RESET_b) ; also on sheet 5 6
SBC_CAN_RX: R137.2 ; also on sheet 5
SBC_CAN_TX: R136.2 ; also on sheet 5
SBC_CS: R129.1 ; also on sheet 5
SBC_LIMP: R532.2 ; also on sheet 5
SBC_MISO: R125.1 ; also on sheet 5
SBC_MOSI: R126.1 ; also on sheet 5
SBC_SCK: R124.1 ; also on sheet 5
SDA_EXTAL: C23.1 U8.17(EXTAL0/PTA18/FTM0_FLT2/FTM_CLKIN0) Y1.3
SDA_JTAG_TCLK: J12.4(B2) U8.12(JTAG_TCLK/SWD_CLK/EZP_CLK/TSI0_CH1/PTA0/~{UART0_CTS}/~{UART0_COL}/FTM0_CH5)
SDA_JTAG_TDI: J12.8(B4) U8.13(JTAG_TDI/EZP_DI/TSI0_CH2/PTA1/UART0_RX/FTM0_CH6)
SDA_JTAG_TDO: J12.6(B3) U8.14(JTAG_TDO/TRACE_SWO/EZP_DO/TSI0_CH3/PTA2/UART0_TX/FTM0_CH7)
SDA_JTAG_TMS: J12.2(B1) R77.2 U8.15(JTAG_TMS/SWD_DIO/TSI0_CH4/PTA3/~{UART0_RTS}/FTM0_CH0)
SDA_LED: D2.C(CATHODE) U8.29(PTD4/SPI0_PCS1/~{UART0_RTS}/FTM0_CH4/EWM_IN/LLWU_P14)
SDA_LED_R: D2.A(ANODE) R12.2
SDA_RST: J12.10(B5) R57.2 R62.1 TP12.1(Pin1) U8.19(~{RESET})
SDA_RST_LED: D1.A(ANODE) R2.1
SDA_RST_TGTMCU_B: J105.2 U8.21(ADC0_SE9/TSI0_CH6/PTB1/I2C0_SDA/FTM1_CH1/FTM1_QD_PHB)
SDA_RST_TGTMCU_J_B: J104.1 J105.1 R3.2 R5.1 U1.2(A1)
SDA_RX_EN: R15.2 R16.1 U4.5(DIR)
SDA_SPI0_CS: R38.2 TP7.1(Pin1) U8.23(ADC0_SE4B/CMP1_IN0/TSI0_CH15/PTC2/SPI0_PCS2/~{UART1_CTS}/FTM0_CH1/I2S0_TX_FS)
SDA_SPI0_RST_B: R41.2 TP8.1(Pin1) U8.22(ADC0_SE15/TSI0_CH14/PTC1/SPI0_PCS3/~{UART1_RTS}/FTM0_CH0/I2S0_TXD0/LLWU_P6)
SDA_SPI0_SCK: U8.26(PTC5/SPI0_SCK/LPTMR0_ALT2/I2S0_RXD0/CMP0_OUT/LLWU_P9) U10.3(A)
SDA_SPI0_SIN: U2.5(2A) U8.28(CMP0_IN1/PTC7/SPI0_SIN/USB_SOF_OUT/I2S0_RX_FS)
SDA_SPI0_SOUT: U7.3(A) U8.27(CMP0_IN0/PTC6/SPI0_SOUT/PDB0_EXTRG/I2S0_RX_BCLK/I2S0_MCLK/LLWU_P10)
SDA_SWD_EN: R41.1 R47.1 U9.6(Y1)
SDA_SWD_EN_B: R49.2 U8.16(~{NMI}/~{EZP_CS}/TSI0_CH5/PTA4/FTM0_CH1/LLWU_P3)
SDA_SWD_EN_B_R: R42.2 R49.1 U9.1(A1)
SDA_SWD_EN_R: R47.2 R51.1 R52.2 U10.5(DIR)
SDA_SWD_OE: R35.1 R38.1 U9.4(Y2)
SDA_SWD_OE_B: R32.2 U8.20(ADC0_SE8/TSI0_CH0/PTB0/I2C0_SCL/FTM1_CH0/FTM1_QD_PHA/LLWU_P5)
SDA_SWD_OE_B_R: R32.1 R39.1 U9.3(A2)
SDA_SWD_OE_R: R30.2 R31.1 R35.2 U7.5(DIR)
SDA_USB_CONN_DN: D19.2(C2) J7.2(D-) R25.1
SDA_USB_CONN_DP: D18.2(C2) J7.3(D+) R21.1
SDA_USB_DN: R25.2 U8.4(USB0_DM)
SDA_USB_DP: R21.2 U8.3(USB0_DP)
SDA_USB_P5V_SENSE: R14.2 R20.1 U8.30(ADC0_SE6B/PTD5/SPI0_PCS2/~{UART0_CTS}/~{UART0_COL}/FTM0_CH5/~{EWM_OUT})
SDA_USBSHIELD: J7.6(SHELL1) J7.7(SHELL2) J7.8(SHELL3) J7.9(SHELL4) J7.10(SHELL5) L2.1
SDA_VOUT33: C9.1 R627.1 U8.5(VOUT33)
SDA_XTAL: C20.1 U8.18(XTAL0/PTA19/FTM1_FLT0/FTM_CLKIN1/LPTMR0_ALT1) Y1.1
SW1_RST_B: C1.1 J104.2 SW5.2 SW5.4
SWD_CLK_TGTMCU_BUF: R626.2 U10.4(B)
SWD_DIO_TGTMCU_BUF: R625.2 U2.2(2B) U7.4(B)
TC_EXTAL_TP: TP11.1(Pin1) U8.10(EXTAL32)
TC_SDA_USB_ID_TP: J7.4(ID) TP6.1(Pin1)
TC_XTAL_TP: TP10.1(Pin1) U8.9(XTAL32)
TP_2102_A: R607.2 U1.3(A2)
TP_2102_B: R608.2 U1.6(B2)
UART1_RX_TGTMCU_BUF: R24.1 U4.4(B)
UART1_RX_TGTMCU_R: U4.3(A) U8.25(PTC4/SPI0_PCS0/UART1_TX/FTM0_CH3/CMP1_OUT/LLWU_P8)
UART1_TX_TGTMCU_BUF: R18.1 U2.1(1B)
UART1_TX_TGTMCU_R: U2.6(1A) U8.24(CMP1_IN1/PTC3/SPI0_PCS1/UART1_RX/FTM0_CH2/I2S0_TX_BCLK/LLWU_P7)
UART_RX: R24.2 R161.1
UART_TX: R18.2 R162.1
V_TGTMCU: C2.1 C4.1 C8.1 R2.2 R4.1 R608.1 SH1.1 U1.8(VCCB) U2.8(VCCB) U4.6(VCCB) U7.6(VCCB) U10.6(VCCB)
VTRG_EN: R68.1 R69.2 R70.2 U11.3(ENABLE)
VTRG_FAULT_B: R60.2 U8.32(PTD7/CMT_IRO/UART0_TX/FTM0_CH7/FTM0_FLT1) U11.4(~{FAULT})
N20337791: R122.2 R662.2 U35.98(PTA4/CMP0_OUT/EWM_OUT_b/JTAG_TMS/SWD_DIO)
N20338052: R123.2 R663.2 U35.92(PTA10/FTM1_CH4/FXIO_D0/JTAG_TDO/noetm_TRACE_SWO)
N20339030: R124.2 R637.2 U35.66(PTB14/FTM0_CH2/LPSPI1_SCK/ADC1_SE9/ADC0_SE9)
N20339144: R125.2 R638.2 U35.65(PTB15/FTM0_CH3/LPSPI1_SIN/ADC1_SE14)
N20339274: R126.2 R640.2 U35.64(PTB16/FTM0_CH4/LPSPI1_SOUT/ADC1_SE15)
N20339954: R128.2 R633.2 U35.95(PTC5/FTM2_CH0/RTC_CLKOUT/FTM2_QD_PHB/JTAG_TDI)
N20342455: R136.1 R659.1 U35.8(PTE5/TCLK2/FTM2_QD_PHA/FTM2_CH3/CAN0_TX/FXIO_D7/EWM_IN)
N20342663: R137.1 R658.1 U35.9(PTE4/FTM2_QD_PHB/FTM2_CH2/CAN0_RX/FXIO_D6/EWM_OUT_b)
N20349379: R161.2 R630.2 U35.81(PTC6/LPUART1_RX/CAN1_RX/FTM3_CH2/FTM1_QD_PHB/ADC1_SE4)
N20349445: R162.2 R632.2 U35.80(PTC7/LPUART1_TX/CAN1_TX/FTM3_CH3/FTM1_QD_PHA/ADC1_SE5)
N20351631: R164.2 R629.2 U35.46(PTC14/FTM1_CH2/TRGMUX_IN9/ADC0_SE12)
N20424711: R154.1 R653.1 U35.22(PTD15/FTM0_CH0/LPSPI0_SCK)
N20424784: R155.1 R655.1 U35.21(PTD16/FTM0_CH1/LPSPI0_SIN/CMP0_RRT)
N20424902: R156.1 R656.1 U35.4(PTD0/FTM0_CH2/LPSPI1_SCK/FTM2_CH0/FXIO_D0/TRGMUX_OUT1)
N20428524: R129.2 R642.2 U35.63(PTB17/FTM0_CH5/LPSPI1_PCS3)
N20428906: R127.2 R634.2 U35.96(PTC4/FTM1_CH0/RTC_CLKOUT/EWM_IN/FTM1_QD_PHB/JTAG_TCLK/SWD_CLK/CMP0_IN2)
N20492371: R529.1 R660.1 U35.23(PTE9/FTM0_CH7)
N20502236: R532.1 R661.1 U35.7(PTE13/FTM2_FLT0)
N20859178: R131.2 R635.2 U35.29(PTC3/FTM0_CH3/CAN0_TX/LPUART0_TX/ADC0_SE11/CMP0_IN4)
N20859231: R130.2 R636.2 U35.30(PTC2/FTM0_CH2/CAN0_RX/LPUART0_RX/ADC0_SE10/CMP0_IN5)
N20864354: R649.1 R650.1 U35.32(PTD6/FTM2_FLT2/CMP0_IN7)
N20864532: R651.1 R652.1 U35.31(PTD7/FTM2_FLT3/CMP0_IN6)
N20866143: R665.2 R666.2 U35.78(PTA1/FTM1_CH1/LPI2C0_SDAS/FXIO_D3/FTM1_QD_PHA/LPUART0_RTS/TRGMUX_OUT0/ADC0_SE1/CMP0_IN1)
N20878661: R569.1 R628.2 TP545.1(Pin1) U35.12(VREFH)
N20880308: J14.9(A5) TP543.1(Pin1)
N20880316: J14.7(A4) TP542.1(Pin1)
N20881189: R667.2 R670.2 U35.54(PTB0/LPUART0_RX/LPSPI0_PCS0/LPTMR0_ALT3/CAN0_RX/ADC0_SE4/ADC1_SE14)
N20881219: R668.2 R669.2 U35.53(PTB1/LPUART0_TX/LPSPI0_SOUT/TCLK0/CAN0_TX/ADC0_SE5/ADC1_SE15)

Not connected (* = marked no-connect by the designer): J12 7(A4)* 9(A5)*

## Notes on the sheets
sheet 1
- OpenSDA Interface
- RESET
- 1-2: Default.
  2-3: Reset signal direct to the MCU,
  to use when OpenSDA is not powered.
- RST Push Button
  Bypass
- TARGET MCU
  INTERFACE
  SIGNALS
- Output to system
  from Level shifter
- UART1_RX_TGTMCU
- Output to system
  from Level shifter
- Isolation
  Resistors
- UART1_TX_TGTMCU
- PU/PD LOGIC:
  SERIAL INTERFACE
  IS ALWAYS RESET
  WHEN USB PORT
  IS DISCONNECTED
- Output to system
  from Level shifter
- SWD_DIO_TGTMCU
- OPEN SDA
  POWER OUTPUTS
- HW Designer: Rafael del Rey
- OPEN SDA
  INPUT POWER
- i
- path
- i
- path
- Note: You can power openSDA
  with your own power supplies
  by replacing this rail
  (SDA_VOUT33)
  with your 3.3V power supply rail
- 3.3VDC, 10mA should be provided
  to this rail (P3V3_SDA)
  in order to power openSDA
  module
- OpenSDA INTERFACE JTAG CONNECTOR
- PWR SWITCH
- Isolation and level shift stage
  (for 1.8 to 5V compatibility)
- PU/PD LOGIC (DIR PIN):
  BUFFER IS TRISTATED WHEN
  P3V3_SDA IS UNPOWERED
- i
- path
- (To enable 5v from
  USB connector)
- SDA_VOUT33 can provide up to 120mA
  of power at 3.3VDC to your system
  P5V_TRG_SDA can provide up to 450mA
  (per USB spec) of power at 5VDC
  to your system
- ACTIVE HIGH
- I/O POWER
  INPUT
- i
- path
- V_BRD is supported
  from 1.8V to 5V
- Power should be provided
  to this rail for the logic
  related to your platform I/O
- {For enablement purposes only}
sheet 2
- SWD Connector
  Programming
sheet 3
- 1. Unless Otherwise Specified:
- All resistors are in ohms,  1% and 5 %
- All capacitors are in uF,  10% , 20 % and  5%
- All voltages are DC
- All polarized capacitors are aluminum electrolytic
- 2. Interrupted lines coded with the same letter or letter
      combinations are electrically connected.
- 3. Device type number is for reference only. The number
      varies with the manufacturer.
- 4. Special signal usage:
- _B Denotes - Active-Low Signal
- <> or [] Denotes - Vectored Signals
- 5. Interpret diagram in accordance with American
  National Standards Institute specifications, current
  revision, with the exception of logic block symbology.
sheet 4
- S32K142EVB-Q100
- C U S T O M E R   E V B
- Table of Contents
- Revisions
- 01   TITLE AND NOTES
- Rev
- Description
- Designer
- Date
- Approved
- 02   Notes and Block Diagram
- X1
- Draft
- J.Sanchez
- 03   S32K142 MCU
- C
- J.Sanchez
- 11/09/17
- 04   OPEN SDA
- D
- Final Release
- J.Sanchez
- 18/09/17
- 05   Power Supply/SWD
- 06   I/Os HEADERS
- C A U T I O N :
- This schematic is provided for reference
  purposes only. As such, NXP does not make any
  warranty, implied or otherwise, as to the
  suitability of circuit design or component
  selection (type or value) used in these
  schematics for hardware design using the  NXP
  S32K family of Microprocessors. Customers using
  any part of these schematics as a basis for
  hardware design, do so at their own risk and
  Freescale does not assume any liability for such
  a hardware design.
- 3 Different test points
  used in design:
  TPVx - Through Hole Pad
  small
  TPHx - Through Hile Pad
  Large (for standard 0.1"
  header). Also used on IO
  Matrix (IOMx)
  TPX  - Surface Mount Wire
  Loop
- Notes:
- - All components and board processes are to be ROHS compliant
  - All connectors and headers are denoted Jx/Px and are 2.54mm pitch unless otherwise stated
  - All jumpers are denoted Jx. Jumpers are 2mm pitch
  - Jumper default positions are shown in the schematics. For 3 way jumpers, default is always
  posn 1-2.
    2 Pin jumpers generally have the "source" on pin 1.
  - All switches are denoted SWx
  - All test points (SMT wire loop style) are denoted TPx
  - Test point Vias (just through hole pads) are denoted TPVx
- Signals (ports) have not been routed via busses as this makes it harder to determine
  where each signal goes.
- User notes are given throughtout the schematics.
- Specific PCB LAYOUT notes are detailed in ITALICS
